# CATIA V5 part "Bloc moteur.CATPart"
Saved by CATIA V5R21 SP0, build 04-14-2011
Part number: bloc moteur
Material "Aluminium": density 2710 kg/m3, Young's modulus 7e+10 Pa, Poisson ratio 0.346, thermal expansion 2.36e-05 1/K
Bounding box of the stored display mesh (mm): x -34 to 34, y -31.5 to 37.5, z -15.714 to 54
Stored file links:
  C:\Users\Utilisateur\Desktop\Fichiers à télécharger dans l'ouvrage\Exercice 9 Pompe de ventilation.CATDrawing (corrigé)\Bloc moteur.CATPart
  C:\Program Files\Dassault Systemes\B21\win_b64\startup\materials\French\Catalog.CATMaterial
  C:\Users\Utilisateur\Desktop\Fichiers à télécharger dans l'ouvrage\Exercice 9 Pompe de ventilation.CATDrawing (corrigé)\CATIA_EnvironmentMap_Satin_512x512.jpg
  C:\Users\Olivier\Desktop\redaction CATIA (local)\pompe à moteur de ventilation refait\Pompe_a_moteur_de_ventilation.CATProduct
  C:\Users\Olivier\Desktop\redaction CATIA (local)\pompe à moteur de ventilation refait\Ecrou a collerette M5.CATPart
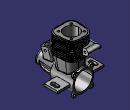
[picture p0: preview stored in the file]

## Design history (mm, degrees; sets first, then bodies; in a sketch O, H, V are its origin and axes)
Body1 (main body), material "Aluminium"
  Sketch1 on yz-plane, origin (0, 0, 0), H (0, 1, 0), V (0, 0, 1)
    line L1 (30, 0) -> (30, -15.5)
    line L2 (30, -15.5) -> (-3.0173, -15.5)
    line L3 (30, 0) -> (-30, 0)
    point P3 (-30, 0)
    line L4 (-30, -9) -> (-6, -11.039)
    point P4 (-30, -9)
    point P5 (-6, -11.039)
    line L5 (-6, -11.039) -> (-3.0173, -15.5)
    line L6 (-30, 0) -> (-30, -9)
    distance P3 P4 = 9
    distance P5 L1 = 36
    length L3 = 60
    length L1 = 15.5
    vertical: L1 V, L6 V
    horizontal: L2 H, L3 H
  Shaft1: profile Sketch1, axis Sketch1.L3, angle 360
  Plane1: type Offset, RefPlane xy-plane, Offset 54
  Sketch2 on Plane1, origin (0, 0, 54), H (1, 0, 0), V (0, 1, 0)
    point P1 (-15.991, -3)
    line L1 (-7.4607, -3) -> (7.4737, -3)
    line L2 (4.6271, 28) -> (-4.6217, 28)
    point P2 (16.009, -3)
    point P3 (14, 28)
    point P4 (-14, 28)
    reference projected line E1 (15.5, 30) -> (-15.5, 30) from edge [face of Shaft1 from Sketch1.L1 | face of Shaft1 from Sketch1.L2]
    line L3 (15.457, 5.5174) -> (14.6061, 18.6467)
    line L4 (-15.4443, 5.5128) -> (-14.6011, 18.6409)
    arc A1 centre (-7.4607, 5) radius 8 from (-7.4607, -3) to (-15.4443, 5.5128) cw
    arc A2 centre (7.4737, 5) radius 8 from (7.4737, -3) to (15.457, 5.5174) ccw
    arc A3 centre (4.6271, 18) radius 10 from (14.6061, 18.6467) to (4.6271, 28) ccw
    arc A4 centre (-4.6217, 18) radius 10 from (-4.6217, 28) to (-14.6011, 18.6409) ccw
    distance E1 L2 = 2
    distance P4 V = 14
    distance P1 P2 = 32
    radius A1 = 8
    radius A2 = 8
    distance P3 P4 = 28
    radius A3 = 10
    radius A4 = 10
    distance L1 L2 = 31
    horizontal: L2 H
    coincidence: L1 P1, L4 P1, L1 P2, L3 P2, L3 P3, L2 P3, L2 P4, L4 P4
    tangency: A1 L1, A1 L4, A2 L1, A2 L3, A3 L3, A3 L2, A4 L2, A4 L4
  Pad1: profile Sketch2, direction (0, 0, -1), length 27
  Sketch3 on end face of Pad1, origin (0, 0, 27), H (1, 0, 0), V (0, -1, 0)
  Sketch4 on end face of Pad1, origin (0, 0, 27), H (1, 0, 0), V (0, -1, 0)
    construction line L1 through (0, 0) direction (1, 0)
    construction line L2 through (0, 0) direction (0, 1)
  Sketch5 on end face of Pad1, origin (0, 0, 27), H (1, 0, 0), V (0, -1, 0)
    reference projected arc E1 centre (-4.6217, -18) radius 10 from (-14.6011, -18.6409) to (-4.6217, -28) ccw from edge [end face of Pad1 | face of Pad1 from Sketch2.A4]
    reference projected arc E2 centre (-7.4607, -5) radius 8 from (-7.4607, 3) to (-15.4443, -5.5128) ccw from edge [end face of Pad1 | face of Pad1 from Sketch2.A1]
    reference projected arc E3 centre (4.6271, -18) radius 10 from (4.6271, -28) to (14.6061, -18.6467) ccw from edge [end face of Pad1 | face of Pad1 from Sketch2.A3]
    line L1 (14.6061, -18.6467) -> (15.457, -5.5174)
    line L2 (7.4737, 3) -> (-7.4607, 3)
    line L3 (-15.4443, -5.5128) -> (-14.6011, -18.6409)
    line L4 (4.6271, -28) -> (-4.6217, -28)
    arc A1 centre (7.4737, -5) radius 8 from (7.4737, 3) to (15.457, -5.5174) cw
    arc A2 centre (4.6271, -18) radius 10 from (14.6061, -18.6467) to (4.6271, -28) cw
    arc A3 centre (-4.6217, -18) radius 10 from (-4.6217, -28) to (-14.6011, -18.6409) cw
    arc A4 centre (-7.4607, -5) radius 8 from (-15.4443, -5.5128) to (-7.4607, 3) cw
    tangency: L1 E3, L2 E2, L3 E1, L4 E1, A1 L1, A2 L4, A3 L3, A4 L2
  Sketch6 on xy-plane, origin (0, 0, 0), H (1, 0, 0), V (0, 1, 0)
    construction line L1 through (0, 0) direction (1, 0)
    construction line L2 through (0, 0) direction (0, 1)
    construction line L3 through (0, 0) direction (1, 0)
    construction line L4 through (0, 0) direction (0, 1)
    point P1 (0, 2.4613)
    construction line L5 through (0, 0) direction (1, 0)
    construction line L6 through (0, 0) direction (0, 1)
    point P2 (-12.8, 0.0613)
    point P3 (12.7992, 0.2685)
    point P4 (11.2, 24.8613)
    point P5 (-11.2, 24.8613)
    line L7 (-5.9184, 0.117) -> (6.0249, 0.2137)
    line L8 (3.7033, 24.8613) -> (-3.6995, 24.8613)
    line L9 (12.3596, 7.0288) -> (11.6864, 17.3804)
    line L10 (-12.3569, 6.9289) -> (-11.6829, 17.3764)
    arc A1 centre (-5.9702, 6.5168) radius 6.4 from (-5.9184, 0.117) to (-12.3569, 6.9289) cw
    arc A2 centre (5.9731, 6.6135) radius 6.4 from (6.0249, 0.2137) to (12.3596, 7.0288) ccw
    arc A3 centre (3.7033, 16.8613) radius 8 from (11.6864, 17.3804) to (3.7033, 24.8613) ccw
    arc A4 centre (-3.6995, 16.8613) radius 8 from (-3.6995, 24.8613) to (-11.6829, 17.3764) ccw
  Loft1: solid, Sections (Sketch5; Sketch6)
  Plane2: type Offset, RefPlane start face of Pad1, Offset 0.5
  Sketch7 on Plane2, origin (0, 0, 53.5), H (1, 0, 0), V (0, -1, 0)
    reference projected curve E1 from start face of Pad1
    construction line L1 through (0, 2.1) direction (1, 0)
    construction line L2 through (0, 2.1) direction (0, 1)
    point P1 (0, 3)
    point P2 (0, 1.25)
    construction line L3 through (0, 1.25) direction (1, 0)
    construction line L4 through (0, 1.25) direction (0, 1)
    point P3 (0, 4.55)
    point P4 (0, -12.5)
    line L5 (8.2211, 4.55) -> (-8.2068, 4.55)
    arc A1 centre (-8.2069, -4.2499) radius 8.7999 from (-8.2068, 4.55) to (-16.9887, -4.814) ccw
    line L6 (-16.9887, -4.814) -> (-16.0612, -19.255)
    arc A2 centre (-5.0839, -18.5501) radius 10.9999 from (-16.0612, -19.255) to (-5.0838, -29.55) ccw
    line L7 (-5.0838, -29.55) -> (5.0898, -29.55)
    arc A3 centre (5.0899, -18.5501) radius 10.9999 from (5.0898, -29.55) to (16.0668, -19.2614) ccw
    line L8 (16.0668, -19.2614) -> (17.0027, -4.8191)
    arc A4 centre (8.2212, -4.2499) radius 8.7999 from (17.0027, -4.8191) to (8.2211, 4.55) ccw
    coincidence: P1 E1, P1 L2
  Pad2: profile Sketch7, direction (0, 0, -1), length 1
  RectPattern1: of Pad2, direction 1 instances 12, spacing 2.2727, along axis of face of Pad1 from Sketch2.A3 reversed
  Sketch8 on start face of Pad1, origin (0, 0, 54), H (1, 0, 0), V (0, 1, 0)
    reference projected line E1 (4.6271, 28) -> (-4.6217, 28) from edge [face of Pad1 from Sketch2.L2 | start face of Pad1]
    point P2 (-4.6217, 28)
    point P3 (-7.4607, -3)
    reference projected line E4 (-14.6011, 18.6409) -> (-15.4443, 5.5128) from edge [face of Pad1 from Sketch2.L4 | start face of Pad1]
    point P7 (-14.6011, 18.6409)
    point P8 (-15.4443, 5.5128)
    circle A1 centre (-9.545, 22.045) radius 1.5
    point P9 (-9.545, 22.045)
    circle A2 centre (-9.545, 2.955) radius 1.5
    point P10 (-9.545, 2.955)
    point P11 (4.6217, 28)
    point P12 (7.4607, -3)
    point P13 (15.4443, 5.5128)
    point P14 (14.6011, 18.6409)
    point P15 (9.545, 22.045)
    circle A3 centre (9.545, 22.045) radius 1.5
    circle A4 centre (9.545, 2.955) radius 1.5
    construction line L1 (14.6011, 18.6409) -> (15.4443, 5.5128)
    circle A5 centre (0, 12.5) radius 10.5
    point P17 (0, 12.5)
    point P18 (0.0027, 28)
    distance P9 P10 = 19.09
    distance P10 V = 9.545
    distance P9 V = 9.545
    distance P15 P17 V = 9.545
    symmetry: P2 P11 V, P3 P12 V, P8 P13 V, P7 P14 V, E4 L1 V, A1 A3 V, A2 A4 V
    coincidence: P17 V
    midpoint: P18 E1
  MultiPocket1: profile Sketch8, domains (length 54; length 8; length 8; length 8; length 8)
  Sketch9 on face of Shaft1 from Sketch1.L1, origin (0, 30, 0), H (-1, 0, 0), V (0, 0, 1)
    circle A1 centre (0, 0) radius 13.25
    circle A2 centre (0, 0) radius 8
  MultiPocket2: profile Sketch9, domains (length 66; length 30)
  Plane3: type Angle, RefPlane face of RectPattern1, Direction edge [face of RectPattern1 | face of RectPattern1], Angle 71
  Sketch10 on Plane3, origin (0.1039, -12.2988, 24.8319), H (-1, -0.0077, -0.0027), V (-0.0082, 0.9455, 0.3256)
    point P1 (0, -8.2811)
    line L1 (7.25, -3.0311) -> (7.25, -13.5311)
    line L2 (5.25, -15.5311) -> (-5.25, -15.5311)
    line L3 (-7.25, -13.5311) -> (-7.25, -3.0311)
    line L4 (-5.25, -1.0311) -> (5.25, -1.0311)
    point P2 (7.25, -15.5311)
    point P3 (-7.25, -15.5311)
    point P4 (-7.25, -1.0311)
    arc A1 centre (-5.25, -3.0311) radius 2 from (-7.25, -3.0311) to (-5.25, -1.0311) cw
    arc A2 centre (5.25, -3.0311) radius 2 from (5.25, -1.0311) to (7.25, -3.0311) cw
    arc A3 centre (5.25, -13.5311) radius 2 from (7.25, -13.5311) to (5.25, -15.5311) cw
    arc A4 centre (-5.25, -13.5311) radius 2 from (-5.25, -15.5311) to (-7.25, -13.5311) cw
    distance P3 P4 = 14.5
    radius A1 = 2
    radius A2 = 2
    distance P2 P3 = 14.5
    radius A3 = 2
    radius A4 = 2
    coincidence: P1 V, L3 P4, L4 P4, L1 P2, L2 P2, L2 P3, L3 P3
    vertical: L1 V, L3 V
    horizontal: L2 H, L4 H
    equidistance: L1 L3 P1, L2 L4 P1
    tangency: A1 L3, A1 L4, A2 L4, A2 L1, A3 L1, A3 L2, A4 L2, A4 L3
  Pad3: profile Sketch10, direction (0, 0.3256, -0.9455), up to the existing solid (limit type 2)
  Sketch11 on start face of Pad3, origin (0.0962, -11.4101, 25.1379), H (1, 0.0077, 0.0027), V (-0.0082, 0.9455, 0.3256)
    circle A1 centre (0, -9.2211) radius 5
    point P1 (0, -9.2211)
    reference projected line E1 (-5.25, -1.9711) -> (5.25, -1.9711) from edge [start face of Pad3 | face of Pad3 from Sketch10.L4]
    distance P1 E1 = 7.25
    coincidence: P1 V
  Pocket1: profile Sketch11, direction (0, 0.3256, -0.9455), through (limit type 6)
  Fillet1: radius 1, on edge [face of Shaft1 from Sketch1.L2 | face of Loft1]; edge [face of Shaft1 from Sketch1.L4 | face of Pad3 from Sketch10.L3]
  Sketch12 on yz-plane, origin (0, 0, 0), H (0, 1, 0), V (0, 0, 1)
    axis line L1 (-14.7367, 0) -> (16.2843, 0)
    point P1 (-14.7367, 0)
    coincidence: P1 H
    horizontal: L1 H
  Plane4: type Angle, RefPlane yz-plane, Direction Sketch12.H, Angle 10
  Sketch13 on Plane4, origin (0, 0, 0), H (0, 1, 0), V (0.1736, 0, 0.9848)
    arc A1 centre (-5.3078, 36.1588) radius 50 from (-3.7677, -13.8175) to (-26.6567, -9.0544) cw
  Stiffener1: ExtendedProfile Sketch13, ThicknessTop 0, ThicknessValue 2
  Plane5: type Angle, RefPlane yz-plane, Direction Sketch12.H, Angle -10
  Sketch14 on Plane5, origin (0, 0, 0), H (0, 1, 0), V (-0.1736, 0, 0.9848)
    arc A1 centre (-5.3078, 36.1588) radius 50 from (-3.7677, -13.8175) to (-26.6567, -9.0544) cw
  Stiffener2: ExtendedProfile Sketch14, ThicknessTop 0, ThicknessValue 2
  CircPattern1: of Stiffener1, Stiffener2, instances 2, angular step 90, axis from face of Shaft1 from Sketch1.L4
  CircPattern2: of Stiffener1, Stiffener2, instances 2, angular step 90, axis from face of Shaft1 from Sketch1.L4
  Sketch15 on yz-plane, origin (0, 0, 0), H (0, 1, 0), V (0, 0, 1)
    construction line L1 (-7.6243, 24.8244) -> (-26.5044, 17.0975)
    point P3 (-12.515, 22.8228)
    coincidence: P3 L1
  Sketch16 on face of Shaft1 from Sketch1.L1, origin (0, 30, 0), H (-1, 0, 0), V (0, 0, 1)
    circle A1 centre (12.7279, 12.7279) radius 1.5
    arc A2 centre (12.7279, 12.7279) radius 3 from (15.2181, 11.0549) to (11.0549, 15.2181) ccw
    line L1 (15.2181, 11.0549) -> (13.5624, 7.5041)
    point P2 (15.2181, 11.0549)
    point P3 (13.5624, 7.5041)
    point P4 (7.5041, 13.5624)
    point P5 (11.0549, 15.2181)
    line L2 (11.0549, 15.2181) -> (7.5041, 13.5624)
    point P7 (-15.2181, 11.0549)
    point P8 (-13.5624, 7.5041)
    point P9 (-7.5041, 13.5624)
    point P10 (-11.0549, 15.2181)
    circle A3 centre (-12.7279, 12.7279) radius 1.5
    arc A4 centre (-12.7279, 12.7279) radius 3 from (-15.2181, 11.0549) to (-11.0549, 15.2181) cw
    line L3 (-15.2181, 11.0549) -> (-13.5624, 7.5041)
    line L4 (-11.0549, 15.2181) -> (-7.5041, 13.5624)
    point P12 (15.2181, -11.0549)
    point P13 (13.5624, -7.5041)
    point P14 (7.5041, -13.5624)
    point P15 (11.0549, -15.2181)
    point P17 (-15.2181, -11.0549)
    point P18 (-13.5624, -7.5041)
    point P19 (-7.5041, -13.5624)
    point P20 (-11.0549, -15.2181)
    circle A5 centre (12.7279, -12.7279) radius 1.5
    arc A6 centre (12.7279, -12.7279) radius 3 from (15.2181, -11.0549) to (11.0549, -15.2181) cw
    line L5 (15.2181, -11.0549) -> (13.5624, -7.5041)
    line L6 (11.0549, -15.2181) -> (7.5041, -13.5624)
    circle A7 centre (-12.7279, -12.7279) radius 1.5
    arc A8 centre (-12.7279, -12.7279) radius 3 from (-15.2181, -11.0549) to (-11.0549, -15.2181) ccw
    line L7 (-15.2181, -11.0549) -> (-13.5624, -7.5041)
    line L8 (-11.0549, -15.2181) -> (-7.5041, -13.5624)
    projected circle E1 centre (0, 0) radius 15.5 from edge [face of Shaft1 from Sketch1.L1 | face of Shaft1 from Sketch1.L2]
    projected arc E2 centre (0, 0) radius 15.5 from (-7.5041, 13.5624) to (-13.5624, 7.5041) ccw from edge [face of Shaft1 from Sketch1.L1 | face of Shaft1 from Sketch1.L2]
    projected arc E3 centre (0, 0) radius 15.5 from (-13.5624, -7.5041) to (-7.5041, -13.5624) ccw from edge [face of Shaft1 from Sketch1.L1 | face of Shaft1 from Sketch1.L2]
    projected arc E4 centre (0, 0) radius 15.5 from (7.5041, -13.5624) to (13.5624, -7.5041) ccw from edge [face of Shaft1 from Sketch1.L1 | face of Shaft1 from Sketch1.L2]
    projected arc E5 centre (0, 0) radius 15.5 from (13.5624, 7.5041) to (7.5041, 13.5624) ccw from edge [face of Shaft1 from Sketch1.L1 | face of Shaft1 from Sketch1.L2]
    radius A2 = 3
    symmetry: P2 P7 V, P3 P8 V, P4 P9 V, P5 P10 V, A1 A3 V, A2 A4 V, L1 L3 V, L2 L4 V, P2 P12 H, P3 P13 H, P4 P14 H, P5 P15 H, P7 P17 H, P8 P18 H, P9 P19 H, P10 P20 H, A1 A5 H, A2 A6 H, L1 L5 H, L2 L6 H, A3 A7 H, A4 A8 H, L3 L7 H, L4 L8 H
  Pad4: profile Sketch16, direction (0, -1, 0), length 2
  Sketch17 on yz-plane, origin (0, 0, 0), H (0, 1, 0), V (0, 0, 1)
    reference projected line E1 through (-11.1809, -3.8499) direction (-0.3256, 0.9455) from axis of face of Pocket1 from Sketch11.A1
    circle A1 centre (-18.5006, 17.4083) radius 1.5
    point P3 (-18.5006, 17.4083)
    reference projected line E2 (-15.1086, 23.8644) -> (-25.0362, 20.446) from edge [start face of Pad3 | face of Pad3 from Sketch10.L3]
    distance P3 E2 = 5
    coincidence: P3 E1
  Pocket2: profile Sketch17, direction (-1, 0, 0), length 9, mirrored extent
  Plane6: type Offset, RefPlane Plane1, Offset 16.5, reversed
  Sketch18 on Plane6, origin (0, 0, 37.5), H (1, 0, 0), V (0, 1, 0)
    projected arc E1 centre (-7.4607, 5) radius 8 from (-15.4443, 5.5128) to (-7.4607, -3) ccw from edge [face of Pad1 from Sketch2.A1 | start face of Pad1]
    point P2 (-7.4607, -3)
    projected line E2 (-7.4607, -3) -> (7.4737, -3) from edge [face of Pad1 from Sketch2.L1 | start face of Pad1]
    projected line E3 (-7.4607, -3) -> (0.0065, -3) from edge [face of Pad1 from Sketch2.L1 | start face of Pad1]
    point P3 (-7.4607, -3)
    projected line E4 (4.6271, 28) -> (-4.6217, 28) from edge [face of Pad1 from Sketch2.L2 | start face of Pad1]
    projected line E5 (0.0027, 28) -> (-4.6217, 28) from edge [face of Pad1 from Sketch2.L2 | start face of Pad1]
    point P6 (-4.6217, 28)
    projected arc E6 centre (-4.6217, 18) radius 10 from (-4.6217, 28) to (-14.6011, 18.6409) ccw from edge [face of Pad1 from Sketch2.A4 | start face of Pad1]
    point P7 (-4.6217, 28)
    projected line E7 (-14.6011, 18.6409) -> (-15.4443, 5.5128) from edge [face of Pad1 from Sketch2.L4 | start face of Pad1]
    line L1 (0.0065, -3) -> (0.0065, -12.5)
    point P11 (0.0065, -3)
    line L2 (0.0065, -12.5) -> (-18.5, -12.5)
    line L3 (-18.5, -12.5) -> (-18.5, 37.5)
    line L4 (-18.5, 37.5) -> (0, 37.5)
    point P15 (0, 37.5)
    line L5 (0, 37.5) -> (0.0027, 28)
    point P16 (0.0027, 28)
    point P17 (0.0046, 12.5)
    distance L2 L4 = 50
    length L4 = 18.5
    midpoint: P11 E2, P16 E4
    vertical: L1 V, L3 V
    horizontal: L2 H, L4 H
    coincidence: P15 V, P2 P3, P6 P7
  Pad5: profile Sketch18, direction (0, 0, 1), length 4.5, mirrored extent
  Sketch19 on face of Pad5 from Sketch18.L5, origin (0.0107, 0, 0), H (-0.0003, 1, 0), V (0, 0, 1)
    circle A1 centre (32.5355, 37.5) radius 1.5
    point P1 (32.5355, 37.5)
    reference projected line E1 (28, 42) -> (37.5, 42) from edge [face of Pad5 from Sketch18.L5 | end face of Pad5]
    reference projected line E2 (37.5, 33) -> (37.5, 42) from edge [face of Pad5 from Sketch18.L4 | face of Pad5 from Sketch18.L5]
    reference projected line E3 (-12.5, 33) -> (-12.5, 42) from edge [face of Pad5 from Sketch18.L1 | face of Pad5 from Sketch18.L2]
    point P2 (37.5, 37.5)
    circle A2 centre (-7.5355, 37.5) radius 1.5
    distance P1 E1 = 4.5
    distance E2 E3 = 50 (reference)
  Pocket3: profile Sketch19, direction (-1, -0.0003, 0), length 8
  Fillet2: radius 4.5, on edge [face of Pad5 from Sketch18.L4 | end face of Pad5]; edge [face of Pad5 from Sketch18.L3 | end face of Pad5]; edge [start face of Pad5 | face of Pad5 from Sketch18.L4]; edge [face of Pad5 from Sketch18.L2 | end face of Pad5]; edge [start face of Pad5 | face of Pad5 from Sketch18.L2]; edge [start face of Pad5 | face of Pad5 from Sketch18.L3]
  Sketch20 on xy-plane, origin (0, 0, 0), H (1, 0, 0), V (0, 1, 0)
    line L1 (13.8085, 26.419) -> (34, 26.419)
    line L2 (34, 26.419) -> (34, 6.419)
    line L3 (34, 6.419) -> (13.7241, 6.419)
    distance L2 V = 34
    length L2 = 20
    horizontal: L1 H, L3 H
    vertical: L2 V
  Stiffener3: ExtendedProfile Sketch20, ThicknessTop 0, ThicknessValue 3.206
  Mirror1: of Stiffener3, about yz-plane
  Sketch21 on face of Stiffener3, origin (0, 0, 1.603), H (1, 0, 0), V (0, 1, 0)
    construction line L1 (28, 19.419) -> (28, 13.419)
    line L2 (31, 19.419) -> (31, 13.419)
    line L3 (25, 13.419) -> (25, 19.419)
    arc A1 centre (28, 13.419) radius 3 from (31, 13.419) to (25, 13.419) cw
    arc A2 centre (28, 19.419) radius 3 from (25, 19.419) to (31, 19.419) cw
    point P3 (31, 19.419)
    point P4 (31, 13.419)
    point P5 (25, 13.419)
    point P6 (25, 19.419)
    point P7 (28, 16.419)
    reference projected line E1 (15.4169, 26.419) -> (34.18, 26.419) from edge [face of Stiffener3 | face of Stiffener3 from Sketch20.L1]
    construction line L4 (-28, 19.419) -> (-28, 13.419)
    point P10 (-31, 19.419)
    point P11 (-31, 13.419)
    point P12 (-25, 13.419)
    point P13 (-25, 19.419)
    point P14 (-28, 16.419)
    line L5 (-31, 19.419) -> (-31, 13.419)
    line L6 (-25, 13.419) -> (-25, 19.419)
    arc A3 centre (-28, 13.419) radius 3 from (-31, 13.419) to (-25, 13.419) ccw
    arc A4 centre (-28, 19.419) radius 3 from (-25, 19.419) to (-31, 19.419) ccw
    distance L1 L2 = 3
    length L1 = 6
    distance P7 E1 = 10
    distance L1 L4 = 56
    vertical: L1 V
    tangency: A1 L2, A2 L2, A1 L3, A2 L3
    midpoint: P7 L1
    symmetry: L1 L4 V, P3 P10 V, P4 P11 V, P5 P12 V, P6 P13 V, P7 P14 V, L2 L5 V, L3 L6 V, A1 A3 V, A2 A4 V
  Pocket4: profile Sketch21, direction (0, 0, -1), length 8
  Plane7: type Offset, RefPlane xy-plane, Offset 54
  Sketch22 on face of Shaft1 from Sketch1.L6, origin (0, -30, 0), H (1, 0, 0), V (0, 0, 1)
    projected circle E1 centre (0, 0) radius 9 from edge [face of Shaft1 from Sketch1.L4 | face of Shaft1 from Sketch1.L6]
    projected circle E2 centre (0, 0) radius 8 from edge [face of Shaft1 from Sketch1.L6 | face of MultiPocket2 from Sketch9.A2]
  Pad6: profile Sketch22, direction (0, -1, 0), length 1.5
